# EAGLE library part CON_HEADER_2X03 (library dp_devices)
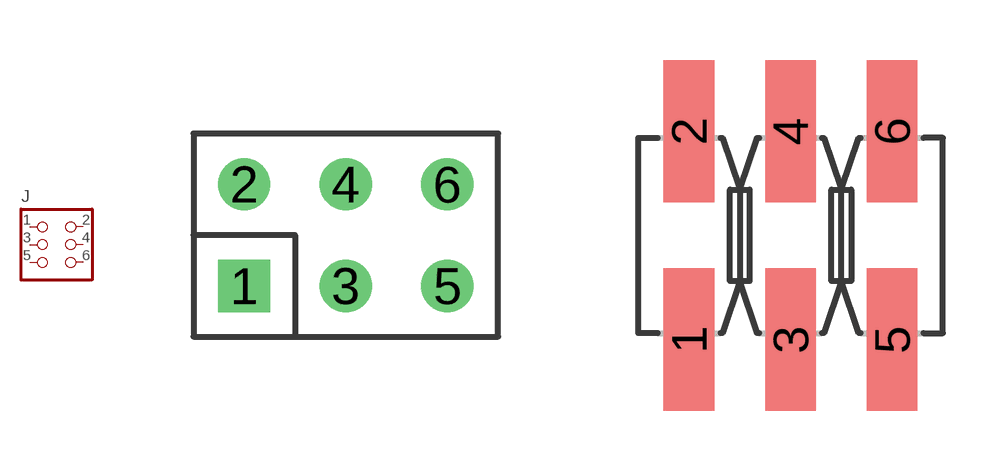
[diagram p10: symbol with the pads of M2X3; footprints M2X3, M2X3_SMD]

Designator prefix J

## CON_HEADER_2X03-PTH  [M2X3]
1  1  pas
2  2  pas
3  3  pas
4  4  pas
5  5  pas
6  6  pas

## CON_HEADER_2X03-SMD  [M2X3_SMD]
Pads as for M2X3

## Footprint M2X3 (pad centres in mm)
drill 0.8 square: 1 -2.54,-1.27
drill 0.8 round: 2 -2.54,1.27; 3 0,-1.27; 4 0,1.27; 5 2.54,-1.27; 6 2.54,1.27

## Footprint M2X3_SMD (pad centres in mm)
2x03 Straight male header SMD Mfr no:5-146134-2 5-146134-2
smd 1.27 x 3.56: 1 -2.54,-2.605; 2 -2.54,2.605; 3 0,-2.605; 4 0,2.605; 5 2.54,-2.605; 6 2.54,2.605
